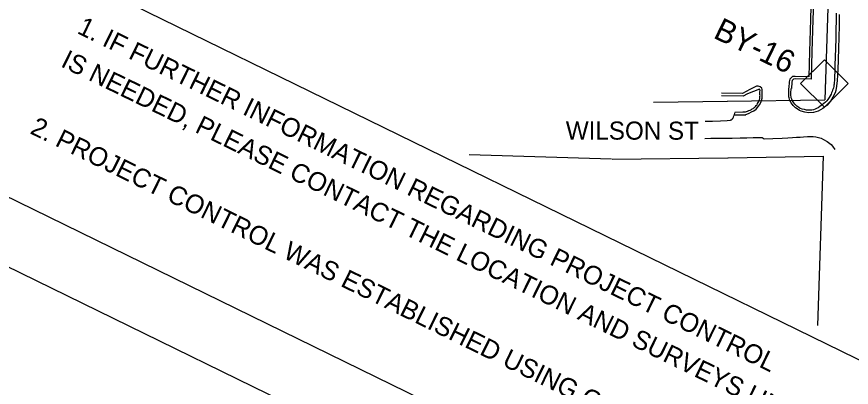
# Model space of a CAD drawing. Extents: x 1517485 to 1521905, y 636528 to 640355.
# Drawn here: x 1519669 to 1520407, y 636995 to 637323 of the extents above; entities that cross this region are included whole.
import ezdxf

# ---------------------------------------------------------------- set-up
doc = ezdxf.new("R2010")
doc.units = 0
for name, color, linetype in [('CTL Secondary Horizontal and Vertical CELL', 7, 'Continuous'), ('CTL Secondary Horizontal and Vertical Text', 7, 'Continuous'), ('CTL Sheet Border CELL', 7, 'Continuous'), ('CTL Sheet Notes CELL', 7, 'Continuous'), ('Exist Right of Way Line', 7, 'Continuous'), ('Exist Roads Curbs', 7, 'Continuous'), ('Exist Roads EOP', 7, 'Continuous'), ('Exist Roads EOP Other', 7, 'Continuous'), ('Exist Roads EOP Text', 7, 'Continuous'), ('Sheet Plot Border Outside CELL', 7, 'Continuous')]:
    doc.layers.add(name, color=color, linetype=linetype)

msp = doc.modelspace()

# ---------------------------------------------------------------- linework, layer by layer
at = {"layer": 'CTL Secondary Horizontal and Vertical CELL'}
msp.add_line((1520383.43, 637263.51), (1520383.43, 637263.51), dxfattribs=at)
msp.add_lwpolyline([(1520362.57, 637263.58), (1520383.54, 637284.54), (1520404.54, 637263.54), (1520383.58, 637242.58)], close=True, dxfattribs=at)
at = {"layer": 'CTL Sheet Border CELL'}
msp.add_lwpolyline([(1521847.18, 638683.19), (1518862.95, 640142.72), (1517841.29, 638053.77), (1520825.52, 636594.25)], close=True, dxfattribs=at)
at = {"layer": 'CTL Sheet Notes CELL'}
msp.add_line((1519701.28, 637367.92), (1520750.63, 636854.7), dxfattribs=at)
at = {"layer": 'Exist Right of Way Line'}
for p, q in [((1520392.38, 637516.53), (1520383.93, 637249.27)), ((1520232.41, 637247.18), (1520297.77, 637247.88)), ((1520297.63, 637247.87), (1520383.93, 637249.27)), ((1520195.38, 637196.8), (1520069.53, 637200.45)), ((1520195.87, 637196.78), (1520298.3, 637197.88)), ((1520298.44, 637197.88), (1520382.35, 637199.24)), ((1520382.35, 637199.24), (1520377.62, 637049.77))]:
    msp.add_line(p, q, dxfattribs=at)
at = {"layer": 'Exist Roads Curbs'}
for points in [[(1520374.17, 637343.49), (1520373.49, 637319.99), (1520372.48, 637291.92), (1520371.83, 637267.31), (1520357.88, 637267.61), (1520356.33, 637267.53), (1520355.14, 637266.38), (1520354.69, 637264.71), (1520354.4, 637259.13)], [(1520394.12, 637325.81), (1520393.95, 637319.11), (1520393.77, 637311.6), (1520393.57, 637303.27), (1520393.34, 637294.96), (1520393.1, 637286.93), (1520392.89, 637280), (1520392.72, 637274.31), (1520392.56, 637269.81), (1520392.43, 637266.48), (1520392.3, 637264.31), (1520392.17, 637263.14), (1520392.01, 637262.05), (1520391.81, 637260.9), (1520391.54, 637259.81), (1520391.19, 637258.78), (1520390.82, 637257.67), (1520390.41, 637256.49), (1520389.97, 637255.35), (1520389.45, 637254.21), (1520388.69, 637252.78), (1520387.71, 637251.09), (1520386.67, 637249.57), (1520385.59, 637248.29), (1520384.45, 637247.09), (1520383.19, 637245.91), (1520381.56, 637244.62), (1520379.63, 637243.24), (1520378, 637242.2), (1520376.72, 637241.53), (1520375.44, 637240.96), (1520374.08, 637240.46), (1520372.59, 637240.11), (1520370.95, 637239.91), (1520369.35, 637239.91), (1520367.76, 637240.09), (1520365.9, 637240.48), (1520363.86, 637241.01), (1520362.49, 637241.46), (1520362.1, 637241.64), (1520361.5, 637242), (1520360.86, 637242.41), (1520360.13, 637242.94), (1520359.25, 637243.66), (1520358.32, 637244.52), (1520357.42, 637245.47), (1520356.64, 637246.44), (1520356.02, 637247.34), (1520355.52, 637248.19), (1520355.09, 637248.99), (1520354.7, 637249.84), (1520354.34, 637250.85), (1520354.06, 637251.91), (1520353.91, 637252.92), (1520353.93, 637254.95), (1520354.15, 637259.11)], [(1520326.61, 637257.97), (1520326.11, 637258.69), (1520315.52, 637254.39), (1520311.64, 637252.53), (1520292.53, 637252.81)], [(1520304.28, 637238.38), (1520311.54, 637238.42), (1520313.22, 637238.49), (1520313.92, 637238.61), (1520314.65, 637238.83), (1520315.66, 637239.19), (1520316.82, 637239.64), (1520317.98, 637240.14), (1520319, 637240.65), (1520319.84, 637241.13), (1520320.54, 637241.58), (1520321.16, 637242.01), (1520321.72, 637242.43), (1520322.25, 637242.87), (1520322.79, 637243.4), (1520323.39, 637244.07), (1520324.01, 637244.88), (1520324.57, 637245.78), (1520325.09, 637246.74), (1520325.55, 637247.73), (1520325.92, 637248.64), (1520326.2, 637249.39), (1520326.4, 637250.14), (1520326.54, 637251.06), (1520326.61, 637252.05), (1520326.64, 637252.99), (1520326.63, 637253.95), (1520326.62, 637255.01), (1520326.63, 637256.19), (1520326.64, 637257.45), (1520326.64, 637257.94)]]:
    msp.add_lwpolyline(points, dxfattribs=at)
at = {"layer": 'Exist Roads EOP'}
for points in [[(1520396.77, 637324.5), (1520396.52, 637314.57), (1520396.25, 637304.61), (1520395.96, 637294.64), (1520395.65, 637284.9), (1520395.34, 637275.79), (1520394.93, 637266.11), (1520394.4, 637261.22), (1520393.61, 637257.27), (1520392.96, 637255.31), (1520391.13, 637251.41), (1520388.97, 637247.88), (1520387.64, 637246.17), (1520386.09, 637244.56), (1520382.27, 637241.61), (1520377.99, 637239.17), (1520376.12, 637238.43), (1520374.02, 637237.98), (1520369.64, 637237.79), (1520366.22, 637238.24), (1520363.05, 637239.17), (1520361.66, 637239.78), (1520360.39, 637240.49), (1520358.08, 637242.16), (1520357.03, 637243.07), (1520356.04, 637244.09), (1520354.33, 637246.36), (1520353.13, 637248.66), (1520352.41, 637250.87), (1520352.18, 637251.95), (1520352, 637254.61), (1520352.15, 637259.35)], [(1520303.96, 637237.72), (1520303.93, 637235.8), (1520309.4, 637235.82), (1520312.44, 637235.93), (1520313.84, 637236), (1520313.95, 637236.01), (1520314.05, 637236.03), (1520314.15, 637236.06), (1520315.02, 637236.45), (1520317.1, 637237.43), (1520319.05, 637238.43), (1520321.05, 637239.57), (1520323.18, 637241.05), (1520324.42, 637242.35), (1520326.25, 637244.62), (1520327.35, 637246.68), (1520327.77, 637247.68), (1520328.08, 637248.67), (1520328.45, 637250.51), (1520328.61, 637252.61), (1520328.63, 637256.72), (1520328.6, 637257.93)], [(1520278.12, 637230.32), (1520284.56, 637230.44), (1520291.72, 637230.64), (1520297.54, 637230.95), (1520300.37, 637231.22), (1520300.67, 637231.28), (1520300.95, 637231.38), (1520301.19, 637231.5), (1520302.02, 637232.16), (1520302.44, 637232.53), (1520302.81, 637232.98), (1520302.97, 637233.24), (1520303.27, 637233.91), (1520303.58, 637234.88), (1520303.86, 637235.63)], [(1520277.85, 637215), (1520283.25, 637215.13), (1520288.93, 637215.23), (1520294.78, 637215.27), (1520302.12, 637215.37), (1520309.23, 637215.57), (1520314.93, 637215.68), (1520320.65, 637215.79), (1520328.41, 637215.75), (1520330.25, 637214.69), (1520337.84, 637214.85), (1520346.11, 637215.21), (1520351.37, 637215.71), (1520355.42, 637216), (1520359.01, 637216.06), (1520362.22, 637216.21), (1520364.97, 637216.5), (1520368.62, 637216.71), (1520372.34, 637216.7), (1520373.73, 637216.64), (1520376.13, 637216.34), (1520378.49, 637215.9), (1520380.78, 637215.16), (1520382.84, 637214.24), (1520385.96, 637212.28), (1520388.45, 637210.6), (1520389.59, 637209.55), (1520390.74, 637208.19), (1520392.7, 637205.17)]]:
    msp.add_lwpolyline(points, dxfattribs=at)
at = {"layer": 'Exist Roads EOP Other'}
for points in [[(1520376.57, 637480.17), (1520375.98, 637461.88), (1520375.36, 637442.8), (1520374.43, 637420.34), (1520373.76, 637395.96), (1520373.12, 637376.59), (1520371.96, 637343.56), (1520371.28, 637320.07), (1520370.26, 637291.99), (1520369.67, 637269.57), (1520357.85, 637269.82), (1520355.39, 637269.7), (1520353.16, 637267.55), (1520352.49, 637265.06), (1520352.21, 637259.8)], [(1520328.68, 637258.27), (1520328.18, 637259.35), (1520326.8, 637260.64), (1520324.97, 637261.12), (1520323.57, 637261.12), (1520317.64, 637258.31), (1520311.15, 637254.74)], [(1520311.15, 637254.74), (1520292.56, 637255.01)]]:
    msp.add_lwpolyline(points, dxfattribs=at)
at = {"layer": 'Sheet Plot Border Outside CELL'}
msp.add_lwpolyline([(1517484.74, 638166.53), (1520835.03, 636527.97), (1521905.33, 638716.38), (1518555.04, 640354.94)], close=True, dxfattribs=at)

# ---------------------------------------------------------------- texts
at = {"layer": 'CTL Secondary Horizontal and Vertical Text'}
msp.add_text('BY-16', height=20, rotation=333.93772, dxfattribs=at).set_placement((1520284.39, 637304.43))
at = {"layer": 'CTL Sheet Notes CELL'}
for s, height, rotation, p in [('1. IF FURTHER INFORMATION REGARDING PROJECT CONTROL', 16.6102, 333.93772, (1519721.84, 637308.42)), ('IS NEEDED, PLEASE CONTACT THE LOCATION AND SURVEYS UNIT.', 16.6102, 333.93772, (1519707.47, 637279.03)), ('2. PROJECT CONTROL WAS ESTABLISHED USING GNSS,  THE GLOBAL NAVIGATION SATELLITE SYSTEM.', 16.6056, 333.83248, (1519680.26, 637219.85))]:
    msp.add_text(s, height=height, rotation=rotation, dxfattribs=at).set_placement(p)
at = {"layer": 'Exist Roads EOP Text'}
msp.add_text('WILSON ST', height=16, rotation=359.88453, dxfattribs=at).set_placement((1520154.89, 637214.07))

doc.saveas('drawing.dxf')
